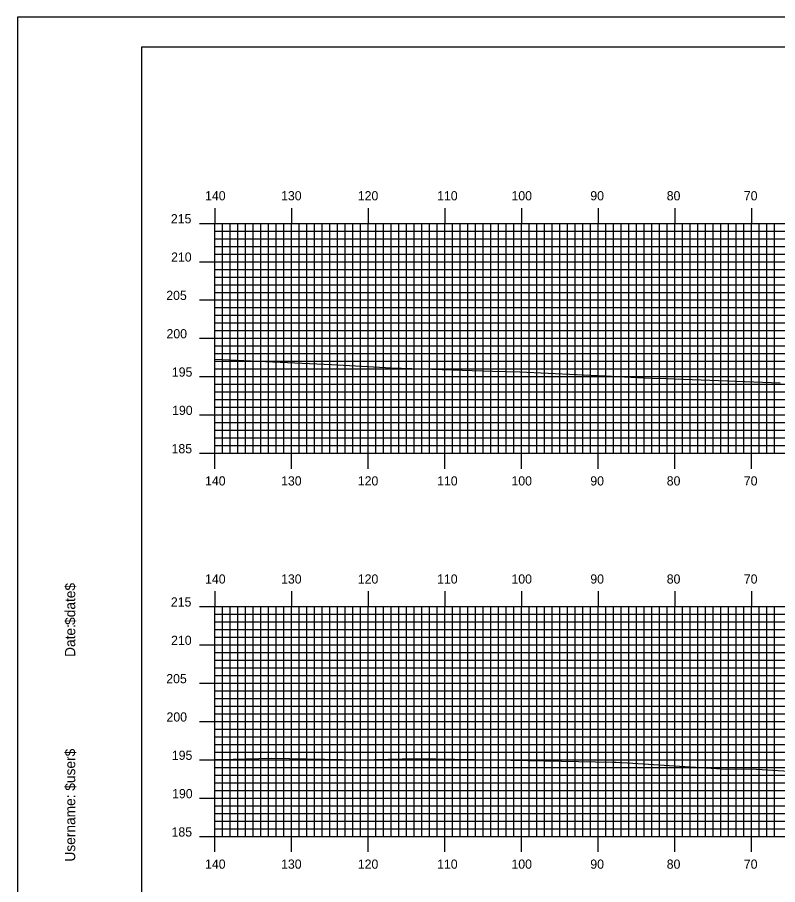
# Model space of a CAD drawing. Extents: x 1815309 to 1815652, y 442591 to 442811.
# Drawn here: x 1815308.7 to 1815408, y 442697.4 to 442810.5 of the extents above; entities that cross this region are included whole.
import ezdxf

# ---------------------------------------------------------------- set-up
doc = ezdxf.new("R2010")
doc.units = 0
for name, color, linetype in [('BORDER', 7, 'Continuous'), ('H_V ANNOTATION', 7, 'Continuous'), ('MAJOR', 7, 'Continuous'), ('MINOR', 7, 'Continuous'), ('PLOT BOUNDARY', 7, 'Continuous'), ('S_Roadway_Centerline', 7, 'Continuous')]:
    doc.layers.add(name, color=color, linetype=linetype)

msp = doc.modelspace()

# ---------------------------------------------------------------- linework, layer by layer
at = {"layer": 'BORDER'}
msp.add_lwpolyline([(1815324.93, 442596.67), (1815644.93, 442596.67), (1815644.93, 442806.67), (1815324.93, 442806.67)], close=True, dxfattribs=at)
at = {"layer": 'MAJOR'}
for p, q in [((1815334.53, 442785.67), (1815334.53, 442783.67)), ((1815344.53, 442785.67), (1815344.53, 442783.67)), ((1815354.53, 442785.67), (1815354.53, 442783.67)), ((1815364.53, 442785.67), (1815364.53, 442783.67)), ((1815374.53, 442785.67), (1815374.53, 442783.67)), ((1815384.53, 442785.67), (1815384.53, 442783.67)), ((1815394.53, 442785.67), (1815394.53, 442783.67)), ((1815404.53, 442785.67), (1815404.53, 442783.67)), ((1815332.53, 442783.67), (1815334.53, 442783.67)), ((1815334.53, 442783.67), (1815614.53, 442783.67)), ((1815334.53, 442753.67), (1815334.53, 442783.67)), ((1815334.53, 442753.67), (1815334.53, 442783.67)), ((1815334.53, 442783.67), (1815614.53, 442783.67)), ((1815344.53, 442753.67), (1815344.53, 442783.67)), ((1815354.53, 442753.67), (1815354.53, 442783.67)), ((1815364.53, 442753.67), (1815364.53, 442783.67)), ((1815374.53, 442753.67), (1815374.53, 442783.67)), ((1815384.53, 442753.67), (1815384.53, 442783.67)), ((1815394.53, 442753.67), (1815394.53, 442783.67)), ((1815404.53, 442753.67), (1815404.53, 442783.67)), ((1815332.53, 442778.67), (1815334.53, 442778.67)), ((1815334.53, 442778.67), (1815614.53, 442778.67)), ((1815332.53, 442773.67), (1815334.53, 442773.67)), ((1815334.53, 442773.67), (1815614.53, 442773.67)), ((1815332.53, 442768.67), (1815334.53, 442768.67)), ((1815334.53, 442768.67), (1815614.53, 442768.67)), ((1815332.53, 442763.67), (1815334.53, 442763.67)), ((1815334.53, 442763.67), (1815614.53, 442763.67)), ((1815332.53, 442758.67), (1815334.53, 442758.67)), ((1815334.53, 442758.67), (1815614.53, 442758.67)), ((1815332.53, 442753.67), (1815334.53, 442753.67)), ((1815334.53, 442753.67), (1815614.53, 442753.67)), ((1815334.53, 442753.67), (1815614.53, 442753.67)), ((1815334.53, 442751.66), (1815334.53, 442753.67)), ((1815344.53, 442751.66), (1815344.53, 442753.67)), ((1815354.53, 442751.66), (1815354.53, 442753.67)), ((1815364.53, 442751.66), (1815364.53, 442753.67)), ((1815374.53, 442751.66), (1815374.53, 442753.67)), ((1815384.53, 442751.66), (1815384.53, 442753.67)), ((1815394.53, 442751.66), (1815394.53, 442753.67)), ((1815404.53, 442751.66), (1815404.53, 442753.67)), ((1815334.53, 442735.67), (1815334.53, 442733.67)), ((1815344.53, 442735.67), (1815344.53, 442733.67)), ((1815354.53, 442735.67), (1815354.53, 442733.67)), ((1815364.53, 442735.67), (1815364.53, 442733.67)), ((1815374.53, 442735.67), (1815374.53, 442733.67)), ((1815384.53, 442735.67), (1815384.53, 442733.67)), ((1815394.53, 442735.67), (1815394.53, 442733.67)), ((1815404.53, 442735.67), (1815404.53, 442733.67)), ((1815332.53, 442733.67), (1815334.53, 442733.67)), ((1815334.53, 442733.67), (1815614.53, 442733.67)), ((1815334.53, 442703.67), (1815334.53, 442733.67)), ((1815334.53, 442703.67), (1815334.53, 442733.67)), ((1815334.53, 442733.67), (1815614.53, 442733.67)), ((1815344.53, 442703.67), (1815344.53, 442733.67)), ((1815354.53, 442703.67), (1815354.53, 442733.67)), ((1815364.53, 442703.67), (1815364.53, 442733.67)), ((1815374.53, 442703.67), (1815374.53, 442733.67)), ((1815384.53, 442703.67), (1815384.53, 442733.67)), ((1815394.53, 442703.67), (1815394.53, 442733.67)), ((1815404.53, 442703.67), (1815404.53, 442733.67)), ((1815332.53, 442728.67), (1815334.53, 442728.67)), ((1815334.53, 442728.67), (1815614.53, 442728.67)), ((1815332.53, 442723.67), (1815334.53, 442723.67)), ((1815334.53, 442723.67), (1815614.53, 442723.67)), ((1815332.53, 442718.67), (1815334.53, 442718.67)), ((1815334.53, 442718.67), (1815614.53, 442718.67)), ((1815332.53, 442713.67), (1815334.53, 442713.67)), ((1815334.53, 442713.67), (1815614.53, 442713.67)), ((1815332.53, 442708.67), (1815334.53, 442708.67)), ((1815334.53, 442708.67), (1815614.53, 442708.67)), ((1815332.53, 442703.67), (1815334.53, 442703.67)), ((1815334.53, 442703.67), (1815614.53, 442703.67)), ((1815334.53, 442703.67), (1815614.53, 442703.67)), ((1815334.53, 442701.66), (1815334.53, 442703.67)), ((1815344.53, 442701.66), (1815344.53, 442703.67)), ((1815354.53, 442701.66), (1815354.53, 442703.67)), ((1815364.53, 442701.66), (1815364.53, 442703.67)), ((1815374.53, 442701.66), (1815374.53, 442703.67)), ((1815384.53, 442701.66), (1815384.53, 442703.67)), ((1815394.53, 442701.66), (1815394.53, 442703.67)), ((1815404.53, 442701.66), (1815404.53, 442703.67))]:
    msp.add_line(p, q, dxfattribs=at)
at = {"layer": 'MINOR'}
for p, q in [((1815335.53, 442753.67), (1815335.53, 442783.67)), ((1815336.53, 442753.67), (1815336.53, 442783.67)), ((1815337.53, 442753.67), (1815337.53, 442783.67)), ((1815338.53, 442753.67), (1815338.53, 442783.67)), ((1815339.53, 442753.67), (1815339.53, 442783.67)), ((1815340.53, 442753.67), (1815340.53, 442783.67)), ((1815341.53, 442753.67), (1815341.53, 442783.67)), ((1815342.53, 442753.67), (1815342.53, 442783.67)), ((1815343.53, 442753.67), (1815343.53, 442783.67)), ((1815345.53, 442753.67), (1815345.53, 442783.67)), ((1815346.53, 442753.67), (1815346.53, 442783.67)), ((1815347.53, 442753.67), (1815347.53, 442783.67)), ((1815348.53, 442753.67), (1815348.53, 442783.67)), ((1815349.53, 442753.67), (1815349.53, 442783.67)), ((1815350.53, 442753.67), (1815350.53, 442783.67)), ((1815351.53, 442753.67), (1815351.53, 442783.67)), ((1815352.53, 442753.67), (1815352.53, 442783.67)), ((1815353.53, 442753.67), (1815353.53, 442783.67)), ((1815355.53, 442753.67), (1815355.53, 442783.67)), ((1815356.53, 442753.67), (1815356.53, 442783.67)), ((1815357.53, 442753.67), (1815357.53, 442783.67)), ((1815358.53, 442753.67), (1815358.53, 442783.67)), ((1815359.53, 442753.67), (1815359.53, 442783.67)), ((1815360.53, 442753.67), (1815360.53, 442783.67)), ((1815361.53, 442753.67), (1815361.53, 442783.67)), ((1815362.53, 442753.67), (1815362.53, 442783.67)), ((1815363.53, 442753.67), (1815363.53, 442783.67)), ((1815365.53, 442753.67), (1815365.53, 442783.67)), ((1815366.53, 442753.67), (1815366.53, 442783.67)), ((1815367.53, 442753.67), (1815367.53, 442783.67)), ((1815368.53, 442753.67), (1815368.53, 442783.67)), ((1815369.53, 442753.67), (1815369.53, 442783.67)), ((1815370.53, 442753.67), (1815370.53, 442783.67)), ((1815371.53, 442753.67), (1815371.53, 442783.67)), ((1815372.53, 442753.67), (1815372.53, 442783.67)), ((1815373.53, 442753.67), (1815373.53, 442783.67)), ((1815375.53, 442753.67), (1815375.53, 442783.67)), ((1815376.53, 442753.67), (1815376.53, 442783.67)), ((1815377.53, 442753.67), (1815377.53, 442783.67)), ((1815378.53, 442753.67), (1815378.53, 442783.67)), ((1815379.53, 442753.67), (1815379.53, 442783.67)), ((1815380.53, 442753.67), (1815380.53, 442783.67)), ((1815381.53, 442753.67), (1815381.53, 442783.67)), ((1815382.53, 442753.67), (1815382.53, 442783.67)), ((1815383.53, 442753.67), (1815383.53, 442783.67)), ((1815385.53, 442753.67), (1815385.53, 442783.67)), ((1815386.53, 442753.67), (1815386.53, 442783.67)), ((1815387.53, 442753.67), (1815387.53, 442783.67)), ((1815388.53, 442753.67), (1815388.53, 442783.67)), ((1815389.53, 442753.67), (1815389.53, 442783.67)), ((1815390.53, 442753.67), (1815390.53, 442783.67)), ((1815391.53, 442753.67), (1815391.53, 442783.67)), ((1815392.53, 442753.67), (1815392.53, 442783.67)), ((1815393.53, 442753.67), (1815393.53, 442783.67)), ((1815395.53, 442753.67), (1815395.53, 442783.67)), ((1815396.53, 442753.67), (1815396.53, 442783.67)), ((1815397.53, 442753.67), (1815397.53, 442783.67)), ((1815398.53, 442753.67), (1815398.53, 442783.67)), ((1815399.53, 442753.67), (1815399.53, 442783.67)), ((1815400.53, 442753.67), (1815400.53, 442783.67)), ((1815401.53, 442753.67), (1815401.53, 442783.67)), ((1815402.53, 442753.67), (1815402.53, 442783.67)), ((1815403.53, 442753.67), (1815403.53, 442783.67)), ((1815405.53, 442753.67), (1815405.53, 442783.67)), ((1815406.53, 442753.67), (1815406.53, 442783.67)), ((1815407.53, 442753.67), (1815407.53, 442783.67)), ((1815334.53, 442782.67), (1815614.53, 442782.67)), ((1815334.53, 442782.67), (1815336.54, 442782.67)), ((1815334.53, 442781.67), (1815614.53, 442781.67)), ((1815334.53, 442781.67), (1815336.54, 442781.67)), ((1815334.53, 442780.67), (1815614.53, 442780.67)), ((1815334.53, 442780.67), (1815336.54, 442780.67)), ((1815334.53, 442779.67), (1815614.53, 442779.67)), ((1815334.53, 442779.67), (1815336.54, 442779.67)), ((1815334.53, 442777.67), (1815614.53, 442777.67)), ((1815334.53, 442777.67), (1815336.54, 442777.67)), ((1815334.53, 442776.67), (1815614.53, 442776.67)), ((1815334.53, 442776.67), (1815336.54, 442776.67)), ((1815334.53, 442775.67), (1815614.53, 442775.67)), ((1815334.53, 442775.67), (1815336.54, 442775.67)), ((1815334.53, 442774.67), (1815614.53, 442774.67)), ((1815334.53, 442774.67), (1815336.54, 442774.67)), ((1815334.53, 442772.67), (1815614.53, 442772.67)), ((1815334.53, 442772.67), (1815336.54, 442772.67)), ((1815334.53, 442771.67), (1815614.53, 442771.67)), ((1815334.53, 442771.67), (1815336.54, 442771.67)), ((1815334.53, 442770.67), (1815614.53, 442770.67)), ((1815334.53, 442770.67), (1815336.54, 442770.67)), ((1815334.53, 442769.67), (1815614.53, 442769.67)), ((1815334.53, 442769.67), (1815336.54, 442769.67)), ((1815334.53, 442767.67), (1815614.53, 442767.67)), ((1815334.53, 442767.67), (1815336.54, 442767.67)), ((1815334.53, 442766.67), (1815614.53, 442766.67)), ((1815334.53, 442766.67), (1815336.54, 442766.67)), ((1815334.53, 442765.67), (1815614.53, 442765.67)), ((1815334.53, 442765.67), (1815336.54, 442765.67)), ((1815334.53, 442764.67), (1815614.53, 442764.67)), ((1815334.53, 442764.67), (1815336.54, 442764.67)), ((1815334.53, 442762.67), (1815614.53, 442762.67)), ((1815334.53, 442762.67), (1815336.54, 442762.67)), ((1815334.53, 442761.67), (1815614.53, 442761.67)), ((1815334.53, 442761.67), (1815336.54, 442761.67)), ((1815334.53, 442760.67), (1815614.53, 442760.67)), ((1815334.53, 442760.67), (1815336.54, 442760.67)), ((1815334.53, 442759.67), (1815614.53, 442759.67)), ((1815334.53, 442759.67), (1815336.54, 442759.67)), ((1815334.53, 442757.67), (1815614.53, 442757.67)), ((1815334.53, 442757.67), (1815336.54, 442757.67)), ((1815334.53, 442756.67), (1815614.53, 442756.67)), ((1815334.53, 442756.67), (1815336.54, 442756.67)), ((1815334.53, 442755.67), (1815614.53, 442755.67)), ((1815334.53, 442755.67), (1815336.54, 442755.67)), ((1815334.53, 442754.67), (1815614.53, 442754.67)), ((1815334.53, 442754.67), (1815336.54, 442754.67)), ((1815335.53, 442703.67), (1815335.53, 442733.67)), ((1815336.53, 442703.67), (1815336.53, 442733.67)), ((1815337.53, 442703.67), (1815337.53, 442733.67)), ((1815338.53, 442703.67), (1815338.53, 442733.67)), ((1815339.53, 442703.67), (1815339.53, 442733.67)), ((1815340.53, 442703.67), (1815340.53, 442733.67)), ((1815341.53, 442703.67), (1815341.53, 442733.67)), ((1815342.53, 442703.67), (1815342.53, 442733.67)), ((1815343.53, 442703.67), (1815343.53, 442733.67)), ((1815345.53, 442703.67), (1815345.53, 442733.67)), ((1815346.53, 442703.67), (1815346.53, 442733.67)), ((1815347.53, 442703.67), (1815347.53, 442733.67)), ((1815348.53, 442703.67), (1815348.53, 442733.67)), ((1815349.53, 442703.67), (1815349.53, 442733.67)), ((1815350.53, 442703.67), (1815350.53, 442733.67)), ((1815351.53, 442703.67), (1815351.53, 442733.67)), ((1815352.53, 442703.67), (1815352.53, 442733.67)), ((1815353.53, 442703.67), (1815353.53, 442733.67)), ((1815355.53, 442703.67), (1815355.53, 442733.67)), ((1815356.53, 442703.67), (1815356.53, 442733.67)), ((1815357.53, 442703.67), (1815357.53, 442733.67)), ((1815358.53, 442703.67), (1815358.53, 442733.67)), ((1815359.53, 442703.67), (1815359.53, 442733.67)), ((1815360.53, 442703.67), (1815360.53, 442733.67)), ((1815361.53, 442703.67), (1815361.53, 442733.67)), ((1815362.53, 442703.67), (1815362.53, 442733.67)), ((1815363.53, 442703.67), (1815363.53, 442733.67)), ((1815365.53, 442703.67), (1815365.53, 442733.67)), ((1815366.53, 442703.67), (1815366.53, 442733.67)), ((1815367.53, 442703.67), (1815367.53, 442733.67)), ((1815368.53, 442703.67), (1815368.53, 442733.67)), ((1815369.53, 442703.67), (1815369.53, 442733.67)), ((1815370.53, 442703.67), (1815370.53, 442733.67)), ((1815371.53, 442703.67), (1815371.53, 442733.67)), ((1815372.53, 442703.67), (1815372.53, 442733.67)), ((1815373.53, 442703.67), (1815373.53, 442733.67)), ((1815375.53, 442703.67), (1815375.53, 442733.67)), ((1815376.53, 442703.67), (1815376.53, 442733.67)), ((1815377.53, 442703.67), (1815377.53, 442733.67)), ((1815378.53, 442703.67), (1815378.53, 442733.67)), ((1815379.53, 442703.67), (1815379.53, 442733.67)), ((1815380.53, 442703.67), (1815380.53, 442733.67)), ((1815381.53, 442703.67), (1815381.53, 442733.67)), ((1815382.53, 442703.67), (1815382.53, 442733.67)), ((1815383.53, 442703.67), (1815383.53, 442733.67)), ((1815385.53, 442703.67), (1815385.53, 442733.67)), ((1815386.53, 442703.67), (1815386.53, 442733.67)), ((1815387.53, 442703.67), (1815387.53, 442733.67)), ((1815388.53, 442703.67), (1815388.53, 442733.67)), ((1815389.53, 442703.67), (1815389.53, 442733.67)), ((1815390.53, 442703.67), (1815390.53, 442733.67)), ((1815391.53, 442703.67), (1815391.53, 442733.67)), ((1815392.53, 442703.67), (1815392.53, 442733.67)), ((1815393.53, 442703.67), (1815393.53, 442733.67)), ((1815395.53, 442703.67), (1815395.53, 442733.67)), ((1815396.53, 442703.67), (1815396.53, 442733.67)), ((1815397.53, 442703.67), (1815397.53, 442733.67)), ((1815398.53, 442703.67), (1815398.53, 442733.67)), ((1815399.53, 442703.67), (1815399.53, 442733.67)), ((1815400.53, 442703.67), (1815400.53, 442733.67)), ((1815401.53, 442703.67), (1815401.53, 442733.67)), ((1815402.53, 442703.67), (1815402.53, 442733.67)), ((1815403.53, 442703.67), (1815403.53, 442733.67)), ((1815405.53, 442703.67), (1815405.53, 442733.67)), ((1815406.53, 442703.67), (1815406.53, 442733.67)), ((1815407.53, 442703.67), (1815407.53, 442733.67)), ((1815334.53, 442732.67), (1815614.53, 442732.67)), ((1815334.53, 442732.67), (1815336.54, 442732.67)), ((1815334.53, 442731.67), (1815614.53, 442731.67)), ((1815334.53, 442731.67), (1815336.54, 442731.67)), ((1815334.53, 442730.67), (1815614.53, 442730.67)), ((1815334.53, 442730.67), (1815336.54, 442730.67)), ((1815334.53, 442729.67), (1815614.53, 442729.67)), ((1815334.53, 442729.67), (1815336.54, 442729.67)), ((1815334.53, 442727.67), (1815614.53, 442727.67)), ((1815334.53, 442727.67), (1815336.54, 442727.67)), ((1815334.53, 442726.67), (1815614.53, 442726.67)), ((1815334.53, 442726.67), (1815336.54, 442726.67)), ((1815334.53, 442725.67), (1815614.53, 442725.67)), ((1815334.53, 442725.67), (1815336.54, 442725.67)), ((1815334.53, 442724.67), (1815614.53, 442724.67)), ((1815334.53, 442724.67), (1815336.54, 442724.67)), ((1815334.53, 442722.67), (1815614.53, 442722.67)), ((1815334.53, 442722.67), (1815336.54, 442722.67)), ((1815334.53, 442721.67), (1815614.53, 442721.67)), ((1815334.53, 442721.67), (1815336.54, 442721.67)), ((1815334.53, 442720.67), (1815614.53, 442720.67)), ((1815334.53, 442720.67), (1815336.54, 442720.67)), ((1815334.53, 442719.67), (1815614.53, 442719.67)), ((1815334.53, 442719.67), (1815336.54, 442719.67)), ((1815334.53, 442717.67), (1815614.53, 442717.67)), ((1815334.53, 442717.67), (1815336.54, 442717.67)), ((1815334.53, 442716.67), (1815614.53, 442716.67)), ((1815334.53, 442716.67), (1815336.54, 442716.67)), ((1815334.53, 442715.67), (1815614.53, 442715.67)), ((1815334.53, 442715.67), (1815336.54, 442715.67)), ((1815334.53, 442714.67), (1815614.53, 442714.67)), ((1815334.53, 442714.67), (1815336.54, 442714.67)), ((1815334.53, 442712.67), (1815614.53, 442712.67)), ((1815334.53, 442712.67), (1815336.54, 442712.67)), ((1815334.53, 442711.67), (1815614.53, 442711.67)), ((1815334.53, 442711.67), (1815336.54, 442711.67)), ((1815334.53, 442710.67), (1815614.53, 442710.67)), ((1815334.53, 442710.67), (1815336.54, 442710.67)), ((1815334.53, 442709.67), (1815614.53, 442709.67)), ((1815334.53, 442709.67), (1815336.54, 442709.67)), ((1815334.53, 442707.67), (1815614.53, 442707.67)), ((1815334.53, 442707.67), (1815336.54, 442707.67)), ((1815334.53, 442706.67), (1815614.53, 442706.67)), ((1815334.53, 442706.67), (1815336.54, 442706.67)), ((1815334.53, 442705.67), (1815614.53, 442705.67)), ((1815334.53, 442705.67), (1815336.54, 442705.67)), ((1815334.53, 442704.67), (1815614.53, 442704.67)), ((1815334.53, 442704.67), (1815336.54, 442704.67))]:
    msp.add_line(p, q, dxfattribs=at)
at = {"layer": 'PLOT BOUNDARY'}
msp.add_lwpolyline([(1815308.75, 442590.55), (1815648.75, 442590.55), (1815648.75, 442810.55), (1815308.75, 442810.55)], close=True, dxfattribs=at)
at = {"layer": 'S_Roadway_Centerline'}
for points in [[(1815334.53, 442765.97), (1815341.14, 442765.66), (1815349.74, 442765.25), (1815357.57, 442764.81), (1815370.75, 442764.37), (1815374.31, 442764.3), (1815385.42, 442763.76), (1815390.53, 442763.52), (1815391.53, 442763.49), (1815393.38, 442763.44), (1815408.3, 442762.88)], [(1815334.53, 442713.71), (1815336.92, 442713.76), (1815341.94, 442713.9), (1815353.47, 442713.68), (1815360.79, 442713.85), (1815370.92, 442713.68), (1815386.39, 442713.39), (1815386.88, 442713.38), (1815388.35, 442713.3), (1815401.31, 442712.45), (1815404.5, 442712.5), (1815409.44, 442712.19)]]:
    msp.add_lwpolyline(points, dxfattribs=at)

# ---------------------------------------------------------------- texts
at = {"layer": 'BORDER'}
for s, p in [('$date$', (1815316.3, 442731.28)), ('Date:', (1815316.3, 442727.1)), ('$user$', (1815316.3, 442709.65)), ('Username:', (1815316.3, 442700.4))]:
    msp.add_text(s, height=1.339, rotation=90, dxfattribs=at).set_placement(p)
at = {"layer": 'H_V ANNOTATION'}
for s, p in [('140', (1815333.24, 442786.67)), ('130', (1815343.16, 442786.67)), ('120', (1815353.17, 442786.67)), ('110', (1815363.52, 442786.67)), ('100', (1815373.22, 442786.67)), ('90', (1815383.51, 442786.67)), ('80', (1815393.48, 442786.67)), ('70', (1815403.54, 442786.67)), ('215', (1815328.78, 442783.67)), ('210', (1815328.81, 442778.67)), ('205', (1815328.18, 442773.67)), ('200', (1815328.21, 442768.67)), ('195', (1815328.91, 442763.67)), ('190', (1815328.94, 442758.67)), ('185', (1815328.87, 442753.67)), ('140', (1815333.24, 442749.47)), ('130', (1815343.16, 442749.47)), ('120', (1815353.17, 442749.47)), ('110', (1815363.52, 442749.47)), ('100', (1815373.22, 442749.47)), ('90', (1815383.51, 442749.47)), ('80', (1815393.48, 442749.47)), ('70', (1815403.54, 442749.47)), ('140', (1815333.24, 442736.67)), ('130', (1815343.16, 442736.67)), ('120', (1815353.17, 442736.67)), ('110', (1815363.52, 442736.67)), ('100', (1815373.22, 442736.67)), ('90', (1815383.51, 442736.67)), ('80', (1815393.48, 442736.67)), ('70', (1815403.54, 442736.67)), ('215', (1815328.78, 442733.67)), ('210', (1815328.81, 442728.67)), ('205', (1815328.18, 442723.67)), ('200', (1815328.21, 442718.67)), ('195', (1815328.91, 442713.67)), ('190', (1815328.94, 442708.67)), ('185', (1815328.87, 442703.67)), ('140', (1815333.24, 442699.47)), ('130', (1815343.16, 442699.47)), ('120', (1815353.17, 442699.47)), ('110', (1815363.52, 442699.47)), ('100', (1815373.22, 442699.47)), ('90', (1815383.51, 442699.47)), ('80', (1815393.48, 442699.47)), ('70', (1815403.54, 442699.47))]:
    msp.add_text(s, height=1.2, dxfattribs=at).set_placement(p)
at = {"layer": 'MAJOR'}
for p in [(1815334.52, 442753.67), (1815334.52, 442703.67)]:
    msp.add_text('-', height=0.012, dxfattribs=at).set_placement(p)

doc.saveas('drawing.dxf')
